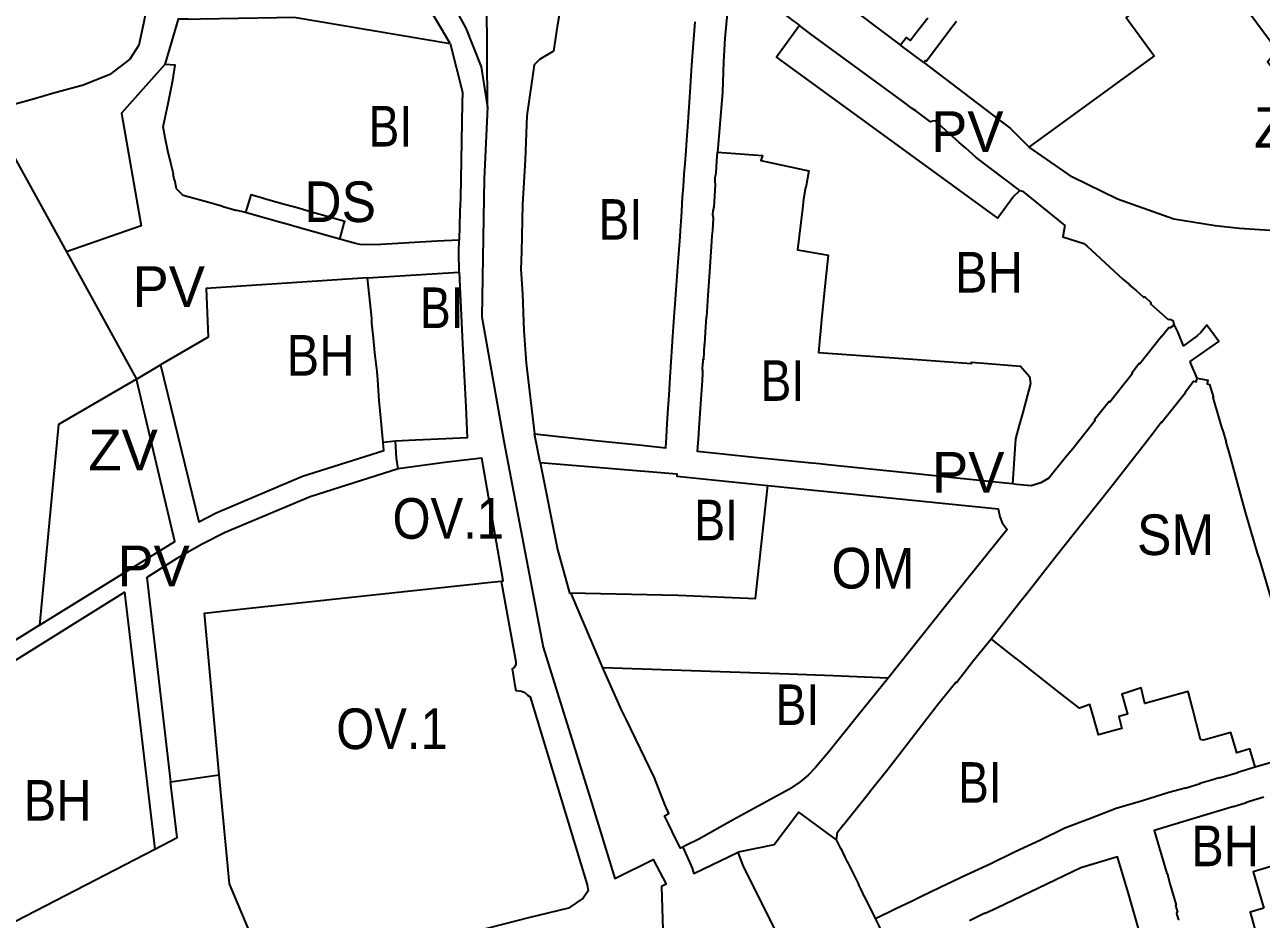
# Model space of a CAD drawing. Extents: x -650451 to -642268, y -1075216 to -1066610.
# Drawn here: x -648055.9 to -647599.3, y -1070638.7 to -1070308.6 of the extents above; entities that cross this region are included whole.
import ezdxf

# ---------------------------------------------------------------- set-up
doc = ezdxf.new("R2010")
doc.units = 0
doc.header["$LTSCALE"] = 6
doc.layers.add('1', color=7, linetype='Continuous', lineweight=35)
doc.layers.add('2', color=7, linetype='Continuous')
doc.layers.add('3', color=7, linetype='Continuous')

msp = doc.modelspace()

# ---------------------------------------------------------------- linework, layer by layer
at = {"layer": '1'}
for p, q in [((-647898.82, -1070315.51), (-647921.51, -1070276.76)), ((-647723.88, -1070322.56), (-647732.45, -1070316.12)), ((-648040.47, -1070392.422), (-648014.63, -1070439.36)), ((-647929.24, -1070401.97), (-647895.46, -1070399.97)), ((-648014.63, -1070439.36), (-648005.668, -1070434.146)), ((-647918.95, -1070462.36), (-647923.53, -1070462.75)), ((-647865.59, -1070470.14), (-647867.58, -1070459.6)), ((-648002, -1070588), (-647984.03, -1070585.46)), ((-648098.637, -1070659.682), (-648007.838, -1070612.851))]:
    msp.add_line(p, q, dxfattribs=at)
for points in [[(-648013.55, -1070211.83), (-648012.15, -1070219.69), (-648010.77, -1070227.39), (-648011.46, -1070227.52), (-648008.62, -1070240.12), (-648005.88, -1070254.37), (-648005.64, -1070276.2), (-648006.32, -1070279.06), (-648008.41, -1070289.81), (-648009.84, -1070297.19), (-648011.99, -1070308.21), (-648013.74, -1070316.1), (-648017.1, -1070321.37), (-648024.41, -1070326.94), (-648034.54, -1070331.05), (-648035.1, -1070331.21), (-648045.61, -1070334.05), (-648052.31, -1070335.9), (-648062.41, -1070338.79)], [(-647855.72, -1070223.34), (-647849.59, -1070228.06), (-647837.19, -1070237.39), (-647835.29, -1070238.81), (-647830.55, -1070242.37), (-647822.44, -1070248.47), (-647814.2, -1070254.66), (-647800.26, -1070265.15), (-647798.3, -1070266.62), (-647779.99, -1070280.38), (-647732.45, -1070316.12)], [(-647884.92, -1070338.99), (-647885.31, -1070280), (-647881.54, -1070229.24)], [(-647856.16, -1070245.75), (-647856.95, -1070295.54), (-647859.2, -1070309.44), (-647860.64, -1070318.32), (-647865.72, -1070321.45), (-647867.72, -1070323.46), (-647870.49, -1070342.22), (-647871.07, -1070358.52), (-647872.08, -1070375), (-647872.46, -1070392.48), (-647872.66, -1070398.77), (-647872.06, -1070408.04), (-647871.52, -1070421.5), (-647870.64, -1070433.56), (-647867.58, -1070459.6)], [(-647543.65, -1070356.3), (-647559.24, -1070368.44), (-647561.41, -1070370.15), (-647597, -1070322.36), (-647593.57, -1070318.03), (-647605.83, -1070301.37), (-647604.97, -1070290.7), (-647599.07, -1070263.04), (-647596.52, -1070260.01), (-647597.32, -1070252.51), (-647597.35, -1070252.24)], [(-647919.915, -1070260.171), (-647918.463, -1070263.562), (-647916.743, -1070266.97), (-647915.023, -1070270.15), (-647909.29, -1070280.15), (-647893.03, -1070309.89), (-647887.295, -1070324.186), (-647884.92, -1070338.99)], [(-647684.99, -1070353.81), (-647638.86, -1070320.16), (-647649.12, -1070306.1), (-647604.1, -1070269.61), (-647605.14, -1070264.04)], [(-647792.79, -1070292.01), (-647795.32, -1070293.08), (-647796.38, -1070303.25), (-647797.29, -1070313.55), (-647797.87, -1070322.32), (-647798.25, -1070333.51), (-647799.78, -1070352.85), (-647800.09, -1070355.7)], [(-647792.79, -1070292.01), (-647776.2, -1070304.14), (-647773.71, -1070305.97), (-647772.1, -1070307.15), (-647771.06, -1070307.92), (-647769.74, -1070308.87)], [(-647995.46, -1070306.55), (-647999.2, -1070306.58), (-648004.11, -1070323.28)], [(-647995.46, -1070306.55), (-647991.12, -1070306.46), (-647962.82, -1070305.9), (-647956.36, -1070305.77), (-647898.82, -1070315.51)], [(-647867.58, -1070459.6), (-647845.11, -1070462.03), (-647829.11, -1070463.7), (-647819.1, -1070464.74), (-647818.88, -1070460.75), (-647818.59, -1070455.9), (-647818.24, -1070450.15), (-647817.92, -1070445.31), (-647817.65, -1070441.19), (-647817.48, -1070438.65), (-647817.28, -1070435.19), (-647817.27, -1070434.91), (-647816.68, -1070425.52), (-647816.66, -1070425.26), (-647816.31, -1070420.13), (-647815.94, -1070414.74), (-647815.74, -1070411.75), (-647815.44, -1070408.17), (-647815.34, -1070406.56), (-647814.61, -1070396.22), (-647813.89, -1070386.91), (-647813.72, -1070384.59), (-647813.45, -1070381.08), (-647813.4, -1070379.52), (-647813.26, -1070377.44), (-647812.94, -1070372.27), (-647812.66, -1070368.32), (-647812.33, -1070363.81), (-647812.05, -1070359.77), (-647811.66, -1070355.12), (-647811.48, -1070352.95), (-647810.91, -1070344.6), (-647810.29, -1070335.39), (-647809.47, -1070323.51), (-647808.31, -1070307.55)], [(-647722.43, -1070306.17), (-647726.93, -1070311.94), (-647728.8, -1070314.42), (-647730.32, -1070313.28), (-647732.45, -1070316.12)], [(-647711.76, -1070307.37), (-647714.33, -1070310.75), (-647716.8, -1070314.02), (-647722.91, -1070322.09), (-647723.302, -1070321.792), (-647723.88, -1070322.56)], [(-647769.74, -1070308.87), (-647778.24, -1070320.54), (-647777.65, -1070321.03), (-647696.62, -1070380.04), (-647691.02, -1070372.29), (-647688.36, -1070369.74)], [(-647688.36, -1070369.74), (-647704.54, -1070357.56), (-647708.43, -1070354.09), (-647710.76, -1070352.02), (-647719.65, -1070344.11), (-647720.5, -1070344.19), (-647721.44, -1070344.48), (-647726.85, -1070340.44), (-647728.14, -1070339.48), (-647731.69, -1070336.82), (-647765.61, -1070312.04), (-647769.74, -1070308.87)], [(-647898.82, -1070315.51), (-647894.22, -1070333.47), (-647894.3, -1070337.61), (-647894.96, -1070372.66), (-647895.09, -1070375.13), (-647895.15, -1070377.65), (-647895.42, -1070388.18)], [(-648004.11, -1070323.28), (-648020.07, -1070341.3), (-648012.846, -1070382.882), (-648040.47, -1070392.422)], [(-647974.28, -1070377.94), (-647977.86, -1070377.01), (-647977.9, -1070377.14), (-647982.7, -1070375.8), (-647982.67, -1070375.67), (-647987.93, -1070374.23), (-647997.34, -1070371.66), (-647999.76, -1070369.16), (-648000.45, -1070366.02), (-648000.59, -1070366.04), (-648001.1, -1070363.75), (-648000.97, -1070363.69), (-648001.86, -1070359.66), (-648002.99, -1070355.18), (-648004.02, -1070350.39), (-648004.68, -1070346.24), (-648002.93, -1070337.72), (-648001.12, -1070329.1), (-648000.34, -1070323.54), (-648004.11, -1070323.28)], [(-647723.88, -1070322.56), (-647696.4, -1070343.48), (-647691.99, -1070346.84), (-647684.99, -1070353.81)], [(-647884.92, -1070338.99), (-647886.21, -1070365.54), (-647887.07, -1070416.41), (-647878.96, -1070462.33), (-647864.39, -1070538.27), (-647847.43, -1070592.87), (-647838.01, -1070623.65), (-647823.823, -1070616.697), (-647819.04, -1070625.82), (-647820.78, -1070626.64), (-647818.97, -1070682.49), (-647788.61, -1070749.59), (-647794.72, -1070752.32), (-647796.81, -1070749.77), (-647799.17, -1070747.87), (-647801.72, -1070747.13), (-647803.86, -1070747.73), (-647803.27, -1070749.84)], [(-648169.69, -1070381.43), (-648062.37, -1070352.64), (-648040.47, -1070392.422)], [(-647691.09, -1070478.1), (-647692.5, -1070477.95), (-647710.45, -1070476.07), (-647730.33, -1070473.97), (-647759.32, -1070471), (-647762.43, -1070470.68), (-647766.54, -1070470.26), (-647786.46, -1070468.28), (-647807.43, -1070466.06), (-647806.96, -1070459.87), (-647806.93, -1070459.34), (-647806.34, -1070450.26), (-647805.63, -1070439.94), (-647805.47, -1070437.28), (-647805.41, -1070436.06), (-647805.62, -1070436.05), (-647805.45, -1070433.37), (-647805.38, -1070433.37), (-647805.29, -1070432.1), (-647805.14, -1070432.11), (-647804.8, -1070426.68), (-647804.73, -1070426.69), (-647804.73, -1070426.6), (-647804.42, -1070422.1), (-647804.53, -1070422.09), (-647804.14, -1070416.46), (-647804.03, -1070416.47), (-647803.5, -1070408.6), (-647802.92, -1070399.8), (-647802.26, -1070390.46), (-647801.97, -1070386.58), (-647801.83, -1070384.58), (-647801.57, -1070380.04), (-647801.74, -1070378.75), (-647801.63, -1070377.27), (-647801.28, -1070375.96), (-647801.01, -1070371.8), (-647800.81, -1070367.54), (-647800.92, -1070366.52), (-647800.89, -1070364.93), (-647800.55, -1070363.45), (-647800.28, -1070358.86), (-647800.09, -1070355.7)], [(-647800.09, -1070355.7), (-647783.48, -1070356.85), (-647784.06, -1070358.77), (-647766.33, -1070362.51), (-647767.43, -1070368.71), (-647767.56, -1070368.67), (-647768.31, -1070372.97), (-647768.62, -1070376.5), (-647770.48, -1070391.66), (-647759.13, -1070393.62), (-647760.13, -1070402.83), (-647761.53, -1070416.2), (-647762.72, -1070429.54), (-647726.25, -1070432.17), (-647706.24, -1070433.62), (-647706.2, -1070433.14), (-647688.11, -1070434.68), (-647687.35, -1070435.56), (-647684.89, -1070438.4), (-647684.44, -1070441.08), (-647687.36, -1070451.73), (-647688.65, -1070456.41), (-647690.04, -1070461.47), (-647691.09, -1070478.1)], [(-647543.65, -1070356.3), (-647540.92, -1070359.89), (-647537.72, -1070365.41), (-647537.79, -1070366.35), (-647542.84, -1070370.3), (-647547.96, -1070373.29), (-647559.2, -1070377.9), (-647574.1, -1070382.54), (-647583.35, -1070384.3), (-647590.57, -1070384.97), (-647607.32, -1070383.77), (-647616.26, -1070382.83), (-647631.54, -1070380.42), (-647652.33, -1070373.02), (-647669.02, -1070364.88), (-647684.99, -1070353.81)], [(-647939.56, -1070387.76), (-647937.87, -1070381.79), (-647937.71, -1070381.22), (-647944.21, -1070379.38), (-647947.24, -1070378.52), (-647950.47, -1070377.61), (-647953.59, -1070376.72), (-647956.63, -1070375.87), (-647959.94, -1070374.93), (-647966.06, -1070373.2), (-647969.33, -1070372.27), (-647972.31, -1070371.43), (-647972.45, -1070371.91), (-647974.28, -1070377.94)], [(-647688.36, -1070369.74), (-647687.43, -1070370.08), (-647671.76, -1070382.66), (-647672.55, -1070386.89), (-647664.81, -1070389.3), (-647663.51, -1070390.33), (-647650.32, -1070402.47), (-647647.79, -1070404.6), (-647647.94, -1070404.76), (-647645.57, -1070406.63), (-647642.91, -1070409.07), (-647642.65, -1070409.3), (-647642.45, -1070409.07), (-647642.39, -1070409.11), (-647642.3, -1070409.01), (-647639.93, -1070411.27), (-647640.03, -1070411.38), (-647639.95, -1070411.43), (-647640.11, -1070411.61), (-647633.68, -1070417.35), (-647632.85, -1070417.28), (-647631.97, -1070417.8), (-647631.52, -1070419.04)], [(-647939.56, -1070387.76), (-647942.64, -1070386.89), (-647949.06, -1070385.07), (-647952.23, -1070384.18), (-647955.32, -1070383.3), (-647958.61, -1070382.37), (-647961.75, -1070381.48), (-647971.35, -1070378.77), (-647974.28, -1070377.94)], [(-647895.42, -1070388.18), (-647903.61, -1070388.55), (-647926.42, -1070389.8), (-647931.94, -1070389.68), (-647933.72, -1070389.41), (-647939.56, -1070387.76)], [(-647895.46, -1070399.97), (-647895.52, -1070392.41), (-647895.42, -1070388.18)], [(-647929.24, -1070401.97), (-647988.86, -1070405.95), (-647988.11, -1070423.93), (-648005.668, -1070434.146)], [(-647923.53, -1070462.75), (-647924.63, -1070451.09), (-647925.02, -1070447.29), (-647925.5, -1070439.63), (-647925.74, -1070436.62), (-647926.53, -1070429.76), (-647926.69, -1070428.19), (-647927.08, -1070424.28), (-647927.67, -1070418.74), (-647927.73, -1070416.98), (-647929.24, -1070401.97)], [(-647895.46, -1070399.97), (-647894.2, -1070426.42), (-647893.61, -1070438.03), (-647893.02, -1070449.58), (-647892.44, -1070461.03), (-647900.39, -1070461.49), (-647911.57, -1070461.98), (-647918.95, -1070462.36)], [(-647631.52, -1070419.04), (-647631.9, -1070419.91), (-647632.9, -1070420.44), (-647633.42, -1070420.46), (-647636.06, -1070423.8), (-647636.13, -1070423.73), (-647644.09, -1070433.78), (-647644.32, -1070433.58), (-647647.11, -1070437.16), (-647646.86, -1070437.37), (-647655.24, -1070447.92), (-647655.48, -1070447.72), (-647660.81, -1070454.45), (-647660.56, -1070454.66), (-647668.89, -1070465.12), (-647671.64, -1070468.42), (-647677.729, -1070475.92), (-647680.64, -1070477.7), (-647684.17, -1070478.8), (-647689.68, -1070478.24), (-647691.09, -1070478.1)], [(-647622.98, -1070439.01), (-647625.24, -1070433.59), (-647625.55, -1070432.84), (-647614.89, -1070425.5), (-647619.42, -1070419.47), (-647621.59, -1070422.15), (-647622.96, -1070423.41), (-647627.97, -1070427.06), (-647630.11, -1070421.96), (-647631.52, -1070419.04)], [(-648005.668, -1070434.146), (-647991.539, -1070492.016), (-647985.19, -1070488.804), (-647953.251, -1070475.276), (-647923.247, -1070465.749), (-647923.53, -1070462.75)], [(-648014.63, -1070439.36), (-648043.43, -1070456.12), (-648050.38, -1070530.2)], [(-648050.38, -1070530.2), (-648000.442, -1070499.336), (-648014.63, -1070439.36)], [(-647699, -1070535.25), (-647688.05, -1070521.29), (-647686.94, -1070519.87), (-647685.86, -1070518.5), (-647674.88, -1070504.49), (-647664.91, -1070491.95), (-647654.26, -1070478.61), (-647641.31, -1070461.98), (-647639.17, -1070459.21), (-647636.18, -1070455.29), (-647636.05, -1070455.39), (-647627.26, -1070444.3), (-647627.38, -1070444.2), (-647624.25, -1070440.21), (-647623.27, -1070440.39), (-647622.98, -1070439.01)], [(-647622.98, -1070439.01), (-647620.34, -1070439.52), (-647618.98, -1070439.77), (-647619.29, -1070441.2), (-647618.34, -1070441.41), (-647616.95, -1070446.19), (-647617.09, -1070446.23), (-647613.76, -1070458.03), (-647613.62, -1070457.99), (-647612.24, -1070462.68), (-647612.37, -1070462.72), (-647611.29, -1070466.4), (-647605.17, -1070488.46), (-647600.42, -1070504.91), (-647600.33, -1070504.88), (-647595.77, -1070520.19)], [(-647917.98, -1070472.47), (-647918.54, -1070468.61), (-647918.95, -1070462.36)], [(-647879.89, -1070513.91), (-647879.16, -1070513.83), (-647887.08, -1070468.54), (-647899.87, -1070470.04), (-647917.98, -1070472.47)], [(-647865.59, -1070470.14), (-647859.18, -1070502.24), (-647854.68, -1070518.29)], [(-647865.59, -1070470.14), (-647815.01, -1070474.33), (-647815.12, -1070475.23), (-647781.43, -1070478.65)], [(-647917.98, -1070472.47), (-647950.48, -1070482.79), (-647981.81, -1070496.06), (-647990.295, -1070500.352), (-647999.756, -1070505.655), (-648010.831, -1070512.588), (-648002, -1070588)], [(-647854.68, -1070518.29), (-647814.55, -1070519.13), (-647785.99, -1070520.38), (-647781.43, -1070478.65)], [(-647781.43, -1070478.65), (-647696.44, -1070487.29), (-647695.82, -1070490.27), (-647694.91, -1070492.48), (-647693.13, -1070494.91), (-647715.98, -1070523.28), (-647737.05, -1070549.71)], [(-647984.03, -1070585.46), (-647989.5, -1070525.73), (-647977.41, -1070524.43), (-647927.14, -1070519), (-647889.27, -1070514.92), (-647886.09, -1070514.58), (-647879.89, -1070513.91)], [(-647879.89, -1070513.91), (-647874.57, -1070543.74), (-647874.57, -1070544.88), (-647875.18, -1070545.86), (-647875.88, -1070546.28), (-647875.79, -1070546.93), (-647875.64, -1070547.77), (-647874.97, -1070551.71), (-647874.48, -1070554.33), (-647872.39, -1070554.51), (-647871.15, -1070555.05), (-647870.17, -1070556.03), (-647869.25, -1070556.63), (-647848.14, -1070626.09), (-647847.8, -1070628.31), (-647849.67, -1070630.94), (-647855.03, -1070634.7), (-647869.87, -1070638.25), (-647907.21, -1070647.84), (-647941.33, -1070659.67), (-647955.81, -1070667.9), (-647961.11, -1070670.91)], [(-648135.47, -1070590.61), (-648019, -1070518), (-648007.838, -1070612.851)], [(-647842.39, -1070545.96), (-647853.97, -1070518.82), (-647854.68, -1070518.29)], [(-648050.38, -1070530.2), (-648122.57, -1070575), (-648137.78, -1070586.25)], [(-647756.13, -1070609.41), (-647755.74, -1070606.59), (-647753.47, -1070603.74), (-647753.39, -1070603.81), (-647752.62, -1070602.85), (-647745.76, -1070594.16), (-647743.8, -1070591.67), (-647743.65, -1070591.47), (-647737.13, -1070583.31), (-647730.85, -1070575.29), (-647724.69, -1070567.22), (-647718.41, -1070559.17), (-647712, -1070551.21), (-647711.81, -1070551.37), (-647705.6, -1070543.36), (-647699, -1070535.25)], [(-647601.55, -1070582.5), (-647603.47, -1070575.9), (-647608.26, -1070577.34), (-647609.15, -1070574.35), (-647610.49, -1070569.86), (-647620.65, -1070572.68), (-647621.64, -1070572.35), (-647624.71, -1070560.83), (-647626.31, -1070554.69), (-647642.21, -1070559.13), (-647643.6, -1070553.3), (-647648.39, -1070554.89), (-647650.76, -1070555.68), (-647650.54, -1070556.45), (-647648.63, -1070563.05), (-647651.9, -1070563.95), (-647650.72, -1070568.29), (-647653.61, -1070569.09), (-647659.39, -1070570.67), (-647661.38, -1070563.65), (-647662.54, -1070559.55), (-647665.58, -1070560.54), (-647666.37, -1070560.79), (-647669.06, -1070558.71), (-647673.96, -1070554.91), (-647676.35, -1070553.05), (-647688.77, -1070543.3), (-647690.2, -1070542.18), (-647692.46, -1070540.39), (-647699, -1070535.25)], [(-647737.05, -1070549.71), (-647757.4, -1070548.94), (-647773.54, -1070548.32), (-647788.08, -1070547.77), (-647842.39, -1070545.96)], [(-647812.82, -1070612.11), (-647813.71, -1070612.56), (-647815.39, -1070609.15), (-647818.19, -1070603.48), (-647819.61, -1070600.59), (-647817.98, -1070599.75), (-647819.55, -1070596.44), (-647823.34, -1070586.53), (-647833.81, -1070564.95), (-647835.51, -1070561.45), (-647842.39, -1070545.96)], [(-647737.05, -1070549.71), (-647747.95, -1070563.36), (-647758.9, -1070576.94), (-647763.83, -1070582.8), (-647766.59, -1070585.58), (-647769.52, -1070587.99), (-647773.75, -1070590.81), (-647783.46, -1070596.13), (-647794.31, -1070602.04), (-647807, -1070609.17), (-647812, -1070611.69), (-647812.82, -1070612.11)], [(-647601.55, -1070582.5), (-647592.1, -1070579.76), (-647592.07, -1070579.85), (-647585.32, -1070577.9), (-647585.35, -1070577.8), (-647581.2, -1070576.55), (-647579.79, -1070573.89)], [(-647961.11, -1070670.91), (-647980.2, -1070625.7), (-647984.03, -1070585.46)], [(-647741.7, -1070638.5), (-647734.17, -1070634.77), (-647728.44, -1070632.04), (-647725.01, -1070630.41), (-647717.77, -1070626.96), (-647708.23, -1070622.36), (-647699.17, -1070618.19), (-647690.11, -1070613.79), (-647680.98, -1070609.51), (-647671.77, -1070605.06), (-647662.28, -1070601.45), (-647652.86, -1070597.72), (-647643.11, -1070594.93), (-647633.4, -1070591.9), (-647627.42, -1070590.22), (-647627.38, -1070590.33), (-647621.83, -1070588.68), (-647621.89, -1070588.54), (-647617.66, -1070587.29), (-647614.79, -1070586.43), (-647614.73, -1070586.57), (-647607.88, -1070584.57), (-647607.93, -1070584.42), (-647601.55, -1070582.5)], [(-648007.838, -1070612.851), (-647999.588, -1070608.596), (-648002, -1070588)], [(-647598.33, -1070593.75), (-647604.79, -1070595.64), (-647604.74, -1070595.77), (-647609.46, -1070597.25), (-647609.48, -1070597.18), (-647611.83, -1070597.85), (-647611.81, -1070597.91), (-647620.49, -1070600.48), (-647638.76, -1070605.98), (-647634.12, -1070621.83), (-647633.98, -1070621.78), (-647632.89, -1070626.04), (-647630.65, -1070633.51), (-647630.93, -1070633.62), (-647630.25, -1070636.1), (-647630.47, -1070636.18), (-647630.57, -1070636.58), (-647629.93, -1070638.72), (-647629.59, -1070638.94)], [(-647756.13, -1070609.41), (-647769.961, -1070599.197), (-647779.08, -1070611.27), (-647792.4, -1070613.99)], [(-647812.82, -1070612.11), (-647810.28, -1070617.88), (-647809.39, -1070619.89), (-647808.99, -1070621.12), (-647808.77, -1070621.81), (-647792.4, -1070613.99)], [(-647741.7, -1070638.5), (-647745.75, -1070630.23), (-647745.84, -1070630.27), (-647746.82, -1070628.04), (-647747.99, -1070625.83), (-647747.9, -1070625.79), (-647751.91, -1070617.72), (-647751.96, -1070617.74), (-647752.9, -1070615.84), (-647752.85, -1070615.82), (-647754.41, -1070612.65), (-647754.49, -1070612.68), (-647756.13, -1070609.41)], [(-647568.43, -1070611.35), (-647580.47, -1070614.85), (-647584.78, -1070616.15), (-647586.75, -1070616.74), (-647596.08, -1070619.45), (-647602.29, -1070621.26), (-647599.15, -1070631.84), (-647598.3, -1070634.71)], [(-647715.3, -1070769.09), (-647790.4, -1070619.27), (-647792.4, -1070613.99)], [(-647644.14, -1070643.84), (-647648.1, -1070630.11), (-647652.31, -1070615.72), (-647665.9, -1070619.71), (-647675.17, -1070624.15), (-647696.95, -1070634.64), (-647701.26, -1070636.68), (-647701.31, -1070636.54), (-647706.97, -1070639.28)], [(-647598.3, -1070634.71), (-647603.37, -1070636.19), (-647593.48, -1070671.67), (-647553.95, -1070659.71)], [(-647732.61, -1070657.08), (-647736.4, -1070649.31), (-647740.59, -1070640.7), (-647741.7, -1070638.5)]]:
    msp.add_lwpolyline(points, dxfattribs=at)

# ---------------------------------------------------------------- texts
at = {"layer": '2'}
for s, width, p in [('BI', 0.85, (-647928.908, -1070353.572)), ('DS', 0.95, (-647952.62, -1070381.442)), ('BI', 0.85, (-647843.984, -1070387.976)), ('BH', 0.9, (-647712.385, -1070407.47)), ('BI', 0.85, (-647909.921, -1070420.574)), ('BI', 0.85, (-647784.159, -1070447.43)), ('BI', 0.85, (-647808.608, -1070498.92)), ('SM', 0.95, (-647645.151, -1070504.337)), ('OM', 0.95, (-647757.96, -1070516.69)), ('BI', 0.85, (-647778.603, -1070567.08)), ('OV.1', 0.9, (-647940.83, -1070575.941)), ('BI', 0.85, (-647711.222, -1070595.77)), ('BH', 0.9, (-647625.147, -1070619.174))]:
    msp.add_text(s, height=15, dxfattribs=dict(at, width=width)).set_placement(p)
for s, p in [('ZX', (-647601.976, -1070354.039)), ('PV', (-647721.185, -1070355.562)), ('PV', (-648016.053, -1070412.76)), ('PV', (-647720.83, -1070481.304))]:
    msp.add_text(s, height=15, dxfattribs=at).set_placement(p)
at = {"layer": '3', "width": 0.9}
for s, p in [('BH', (-647959.167, -1070438.127)), ('OV.1', (-647920.041, -1070498.314)), ('BH', (-648056.286, -1070602.34))]:
    msp.add_text(s, height=15, dxfattribs=at).set_placement(p)
at = {"layer": '3'}
for s, p in [('ZV', (-648032.359, -1070473.105)), ('PV', (-648021.637, -1070515.856))]:
    msp.add_text(s, height=15, dxfattribs=at).set_placement(p)

doc.saveas('drawing.dxf')
